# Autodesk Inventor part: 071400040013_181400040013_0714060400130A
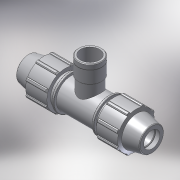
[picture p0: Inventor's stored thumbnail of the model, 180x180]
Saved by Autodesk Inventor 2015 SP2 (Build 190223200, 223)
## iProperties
Created: 2017-02
Part Number: 071400040013_181400040013_0714060400130A
Material: PVC-Piping
Description: PLASSON TEE WITH THREADED FEMALE OFFTAKE 40-1.1/4"-40
Document SubType Name: Modeling
Designer: KIM
Mass: 92.6774 g
Surface Area: 199.44 cm^2
Volume: 66.1981 cm^3
Density: 1.4 g/cm^3
Appearance: Smooth - White
Author: KIM
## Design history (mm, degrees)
derived "07140.ipt"
feature "Solid1::07140.ipt"
feature "Solid2::07140.ipt"
tag "TaggingFeature1"
body "Solid1"
other parameters: "d4" = 9.04167, "d5" = 26.04, "d7" = 82, "d11" = 3.61667, "d13" = 120 deg, "d15" = 12 deg, "d16" = 71.34, "d18" = 2, "d19" = 35 deg, "d20" = 17.5 deg, "d21" = 76.26, "d23" = 0, "d25" = 360 deg, "d27" = 1.64, "d33" = 0.8, "d42" = 39.06, "d43" = 2.46, "d46" = 1.2, "d68" = 6.51, "d76" = 38.952, "d80" = 1.16856, "d91" = 61.5, "d93" = 84, "d95" = 36, "d112" = 24, "d115" = 48.69, "d116" = 135 deg, "d117" = 44.7948, "d118" = 217, "d119" = 36, "d121" = 0, "d122" = 36, "d124" = 0, "d128" = 0, "d129" = 4, "d130" = 7.2, "d131" = 0.3, "d132" = 0.3, "d133" = 48.69, "E_" = 82, "l_" = 84, "l_2" = 24, "Rp_" = 38.952, "H_" = 217
